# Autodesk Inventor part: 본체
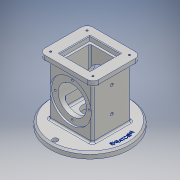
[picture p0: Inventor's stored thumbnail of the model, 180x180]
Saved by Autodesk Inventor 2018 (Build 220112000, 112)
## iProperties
Created: 2019-08
Part Number: 본체
Material: 알루미늄 6061
Document SubType Name: Modeling
Designer: USER
Density: 2.7 g/cm^3
Appearance: 알루미늄 - 평지
Mass: 1038.84 g
Surface Area: 783.572 cm^2
Volume: 384.756 cm^3
Author: USER
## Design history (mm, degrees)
sketch "스케치2"
  geometry: C1 r 67.5 at (0, 0); 1 further point
  constraints: 1 centre point, 1 coincident
  dimensions: "d1" = 135 diameter of C1
extrude "돌출1" new body sketch "스케치2" distance "d2" = 10; taper "d3" = 0 deg
sketch "스케치3" dims "d4" = 118
  geometry: C1 r 4.5 at (0, 59); 2 further points
  constraints: 2 vertical alignment, 1 centre point, 1 coincident, 2 other
  dimensions: "d5" = 9 diameter of C1
extrude "돌출2" cut sketch "스케치3" extent not by distance; stored distance "d6" = 10; taper "d7" = 0 deg
sketch "스케치4" dims "d11" = 118
  geometry: C1 r 4.5 at (-59, 0); 2 further points
  constraints: 2 horizontal alignment, 1 centre point, 1 coincident, 2 other
  dimensions: "d12" = 9 diameter of C1
extrude "돌출3" cut sketch "스케치4" extent not by distance; stored distance "d13" = 10; taper "d14" = 0 deg
sketch "스케치5"
  geometry: L1 (37, -33)-(-37, -33); L2 (-37, -33)-(-37, 33); L3 (-37, 33)-(37, 33); L4 (37, 33)-(37, -33); L5 (37, -33)-(-37, 33); L6 (-37, -33)-(37, 33); 1 further point
  constraints: 12 end point, 2 midpoint, 2 parallel, 1 horizontal, 1 perpendicular
  dimensions: "d15" = 74 distance of L2.end L3.end; "d16" = 66 distance of L1.end L2.end
extrude "돌출4" join sketch "스케치5" distance "d17" = 88; taper "d18" = 0 deg
node "스케치6"
sketch "스케치7"
  geometry: L1 (46, -41)-(-46, -41); L2 (-46, -41)-(-46, 41); L3 (-46, 41)-(46, 41); L4 (46, 41)-(46, -41); L5 (46, -41)-(-46, 41); L6 (-46, -41)-(46, 41); 1 further point
  constraints: 12 end point, 2 midpoint, 2 parallel, 1 horizontal, 1 perpendicular
  dimensions: "d19" = 92 distance of L2.end L3.end; "d20" = 82 distance of L1.end L2.end
extrude "돌출5" join sketch "스케치7" distance "d21" = 10; taper "d22" = 0 deg
sketch "스케치8"
  geometry: L1 (-30.5, -10)-(104.5, -10) reference; C1 r 35 at (37, 44); 2 further points
  constraints: 1 centre point, 1 midpoint, 1 vertical alignment
  dimensions: "d23" = 70 diameter of C1; "d24" = 54 distance from line of L1 C1.centre
extrude "돌출6" cut sketch "스케치8" distance "d25" = 3; taper "d26" = 0 deg
sketch "스케치9"
  geometry: C1 r 24 at (0, 0); C2 r 35 at (0, 0) reference; 1 further point
  constraints: 1 centre point, 1 concentric
  dimensions: "d27" = 48 diameter of C1
extrude "돌출7" cut sketch "스케치9" extent not by distance; stored distance "d28" = 3; taper "d29" = 0 deg
sketch "스케치10" dims "d30" = 58
  geometry: C1 r 35 at (0, 0) reference; 3 further points
  constraints: 2 vertical alignment, 3 other
hole "구멍1" sketch "스케치10" at (0, 29) diameter "d31" = 3.242; stored, may be unused: countersink angle "d35" = 90 deg, drill point angle "d37" = 118 deg; dims "d32" = 4, "d33" = 4, "d34" = 2, "d36" = 6
sketch "스케치11"
  geometry: L1 (26, -26)-(-26, -26); L2 (-26, -26)-(-26, 26); L3 (-26, 26)-(26, 26); L4 (26, 26)-(26, -26); L5 (26, -26)-(-26, 26); L6 (-26, -26)-(26, 26); 1 further point
  constraints: 12 end point, 2 midpoint, 2 parallel, 1 horizontal, 1 perpendicular
  dimensions: "d41" = 52 distance of L2.end L3.end; "d42" = 52 distance of L1.end L2.end
extrude "돌출8" cut sketch "스케치11" distance "d43" = 8; taper "d44" = 0 deg
sketch "스케치12"
  geometry: L1 (-22, -22)-(22, -22); L2 (22, -22)-(22, 22); L3 (22, 22)-(-22, 22); L4 (-22, 22)-(-22, -22); L5 (-22, -22)-(22, 22); L6 (22, -22)-(-22, 22); 1 further point
  constraints: 12 end point, 2 midpoint, 2 parallel, 1 horizontal, 1 perpendicular
  dimensions: "d45" = 44 distance of L2.end L3.end; "d46" = 44 distance of L3.end L1.start
extrude "돌출9" cut sketch "스케치12" distance "d47" = 74; taper "d48" = 0 deg
sketch "스케치13"
  geometry: C1 r 25 at (0, 0); C2 r 67.5 at (0, 0) reference; 1 further point
  constraints: 1 centre point, 1 coincident, 1 concentric
  dimensions: "d49" = 50 diameter of C1
extrude "돌출10" cut sketch "스케치13" distance "d50" = 18; taper "d51" = 0 deg
sketch "스케치14"
  geometry: C1 r 12.5 at (0, 0); C2 r 25 at (0, 0) reference; 1 further point
  constraints: 1 centre point, 1 coincident, 1 concentric
  dimensions: "d52" = 25 diameter of C1
extrude "돌출11" cut sketch "스케치14" extent not by distance; stored distance "d53" = 18; taper "d54" = 0 deg
fillet "모깎기1" dims "d55" = 3
chamfer "모따기1" distance "d56" = 1; stored, may be unused: second distance "d57" = 2, angle "d58" = 45 deg
fillet "모깎기2" dims "d59" = 3
fillet "모깎기3" dims "d60" = 3
fillet "모깎기4" dims "d61" = 10
fillet "모깎기5" dims "d62" = 3
fillet "모깎기6" dims "d63" = 3
sketch "스케치15"
  geometry: L1 (36, -31)-(-36, -31); L2 (-36, -31)-(-36, 31); L3 (-36, 31)-(36, 31); L4 (36, 31)-(36, -31); L5 (36, -31)-(-36, 31); L6 (-36, -31)-(36, 31); C1 r 25 at (0, 0) reference; 5 further points
  constraints: 12 end point, 4 coincident, 2 midpoint, 2 parallel, 1 horizontal, 1 perpendicular
  dimensions: "d64" = 72 distance of L2.end L3.end; "d65" = 62 distance of L3.end L1.start
hole "구멍2" sketch "스케치15" at (-36, 31), (-36, -31), (36, -31), (36, 31) diameter "d66" = 3.242; stored, may be unused: countersink angle "d70" = 90 deg, drill point angle "d72" = 118 deg; dims "d67" = 4, "d68" = 4, "d69" = 2, "d71" = 6
sketch "스케치16"
  geometry: L1 (13, -37.5)-(13, 97.5) reference; 3 further points
  constraints: 2 horizontal alignment
  dimensions: "d73" = 37 distance from line of point (-24, 30) L1; "d74" = 43 distance of point (-67, 30) point (-24, 30)
hole "구멍3" sketch "스케치16" at (-67, 30), (-24, 30) diameter "d75" = 4.917; stored, may be unused: countersink angle "d79" = 90 deg, drill point angle "d81" = 118 deg; dims "d76" = 28, "d77" = 4, "d78" = 2, "d80" = 30
fillet "모깎기7" dims "d82" = 3
sketch "스케치17"
  geometry: C1 r 59 at (0, 0); 1 further point
  constraints: 1 centre point, 1 coincident, 1 other
  dimensions: "d83" = 118 diameter of C1
feature "엠보싱1" sketch "스케치17" dims "d84" = 0.5, "d85" = 0
chamfer "모따기2" distance "d86" = 3; stored, may be unused: second distance "d87" = 2, angle "d88" = 45 deg
node "솔리드1"
mirror "미러1"
pattern_circular "원형 패턴2" dims angle "d39" = 360 deg
mirror "미러2"
